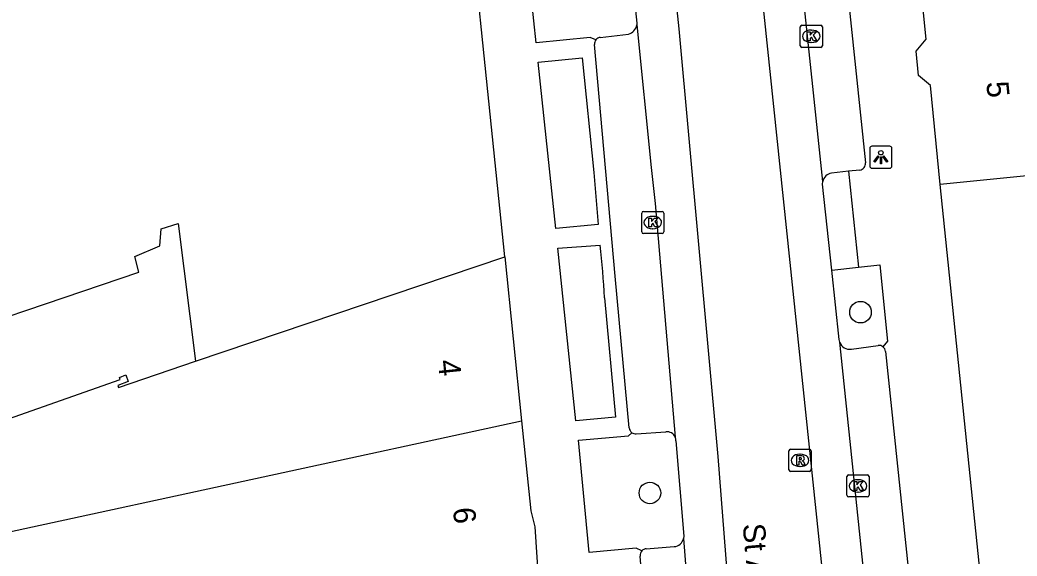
# Model space of a CAD drawing. Extents: x 159718 to 160783, y 383290 to 384030.
# Drawn here: x 160558.03 to 160603.13, y 383377.04 to 383401.3 of the extents above; entities that cross this region are included whole.
import ezdxf

# ---------------------------------------------------------------- set-up
doc = ezdxf.new("R2010")
doc.units = 0
for name, color, linetype in [('IMGEO_Boom', 7, 'Continuous'), ('IMGEO_Kolk', 7, 'Continuous'), ('IMGEO_Lichtpunt', 7, 'Continuous'), ('IMGEO_Openbare_ruimte_label', 7, 'Continuous'), ('IMGEO_Pand', 7, 'Continuous'), ('IMGEO_Pand_nummerreeks', 7, 'Continuous'), ('IMGEO_Parkeervlak_open', 7, 'Continuous'), ('IMGEO_Rijbaan_lokaal_gesloten', 7, 'Continuous'), ('IMGEO_Rioolput', 7, 'Continuous'), ('IMGEO_Voetpad_open', 7, 'Continuous')]:
    doc.layers.add(name, color=color, linetype=linetype)

msp = doc.modelspace()

# ---------------------------------------------------------------- linework, layer by layer
at = {"layer": 'IMGEO_Boom'}
for centre in [(160596.052, 383388.077), (160586.528, 383379.895)]:
    msp.add_circle(centre, 0.489, dxfattribs=at)
at = {"layer": 'IMGEO_Kolk'}
for p, q in [((160593.325, 383400.137), (160593.325, 383400.989)), ((160593.4, 383401.063), (160594.252, 383401.063)), ((160593.813, 383400.843), (160593.838, 383400.843)), ((160594.326, 383400.989), (160594.326, 383400.137)), ((160594.252, 383400.063), (160593.4, 383400.063)), ((160593.836, 383400.283), (160593.811, 383400.283)), ((160586.229, 383392.635), (160587.081, 383392.635)), ((160586.154, 383391.709), (160586.154, 383392.561)), ((160586.642, 383392.415), (160586.667, 383392.415)), ((160587.155, 383392.561), (160587.155, 383391.709)), ((160586.665, 383391.855), (160586.64, 383391.855)), ((160587.081, 383391.635), (160586.229, 383391.635)), ((160595.439, 383379.788), (160595.439, 383380.64)), ((160595.514, 383380.714), (160596.366, 383380.714)), ((160595.927, 383380.494), (160595.952, 383380.494)), ((160596.44, 383380.64), (160596.44, 383379.788)), ((160596.366, 383379.714), (160595.514, 383379.714)), ((160595.95, 383379.934), (160595.925, 383379.934))]:
    msp.add_line(p, q, dxfattribs=at)
for points in [[(160593.325, 383400.137), (160593.325, 383400.989)], [(160593.4, 383401.063), (160594.252, 383401.063)], [(160593.646, 383400.763), (160593.769, 383400.763), (160593.769, 383400.612), (160593.899, 383400.763), (160594.063, 383400.763), (160593.917, 383400.612), (160594.07, 383400.363), (160593.918, 383400.363), (160593.833, 383400.527), (160593.769, 383400.46), (160593.769, 383400.363), (160593.646, 383400.363), (160593.646, 383400.763)], [(160594.326, 383400.989), (160594.326, 383400.137)], [(160594.252, 383400.063), (160593.4, 383400.063)], [(160586.229, 383392.635), (160587.081, 383392.635)], [(160586.154, 383391.709), (160586.154, 383392.561)], [(160586.475, 383392.335), (160586.598, 383392.335), (160586.598, 383392.184), (160586.728, 383392.335), (160586.892, 383392.335), (160586.746, 383392.184), (160586.899, 383391.935), (160586.747, 383391.935), (160586.662, 383392.099), (160586.598, 383392.032), (160586.598, 383391.935), (160586.475, 383391.935), (160586.475, 383392.335)], [(160587.155, 383392.561), (160587.155, 383391.709)], [(160587.081, 383391.635), (160586.229, 383391.635)], [(160595.439, 383379.788), (160595.439, 383380.64)], [(160595.514, 383380.714), (160596.366, 383380.714)], [(160596.44, 383380.64), (160596.44, 383379.788)], [(160595.76, 383380.414), (160595.883, 383380.414), (160595.883, 383380.263), (160596.013, 383380.414), (160596.177, 383380.414), (160596.031, 383380.263), (160596.184, 383380.014), (160596.032, 383380.014), (160595.947, 383380.178), (160595.883, 383380.111), (160595.883, 383380.014), (160595.76, 383380.014), (160595.76, 383380.414)], [(160596.366, 383379.714), (160595.514, 383379.714)]]:
    msp.add_lwpolyline(points, dxfattribs=at)
for centre, start, end in [((160593.402, 383400.987), 91.552, 178.448), ((160593.402, 383400.987), 91.552, 178.448), ((160594.25, 383400.987), 1.552, 88.448), ((160594.25, 383400.987), 1.552, 88.448), ((160593.402, 383400.139), 181.552, 268.448), ((160593.402, 383400.139), 181.552, 268.448), ((160594.25, 383400.139), 271.552, 358.448), ((160594.25, 383400.139), 271.552, 358.448), ((160586.231, 383392.559), 91.552, 178.448), ((160586.231, 383392.559), 91.552, 178.448), ((160587.079, 383392.559), 1.552, 88.448), ((160587.079, 383392.559), 1.552, 88.448), ((160586.231, 383391.711), 181.552, 268.448), ((160586.231, 383391.711), 181.552, 268.448), ((160587.079, 383391.711), 271.552, 358.448), ((160587.079, 383391.711), 271.552, 358.448), ((160595.516, 383380.638), 91.552, 178.448), ((160595.516, 383380.638), 91.552, 178.448), ((160596.364, 383380.638), 1.552, 88.448), ((160596.364, 383380.638), 1.552, 88.448), ((160595.516, 383379.79), 181.552, 268.448), ((160595.516, 383379.79), 181.552, 268.448), ((160596.364, 383379.79), 271.552, 358.448), ((160596.364, 383379.79), 271.552, 358.448)]:
    msp.add_arc(centre, 0.0765, start, end, dxfattribs=at)
for centre, major_axis, ratio, start_param, end_param in [((160593.812, 383400.563), (-0.387, 0.002), 0.722429, 4.712389, 7.853982), ((160593.837, 383400.563), (-0.39, 0.002), 0.717154, 1.570796, 4.712389), ((160586.641, 383392.135), (-0.387, 0.002), 0.722429, 4.712389, 7.853982), ((160586.666, 383392.135), (-0.39, 0.002), 0.717154, 1.570796, 4.712389), ((160595.926, 383380.214), (-0.387, 0.002), 0.722429, 4.712389, 7.853982), ((160595.951, 383380.214), (-0.39, 0.002), 0.717154, 1.570796, 4.712389)]:
    msp.add_ellipse(centre, major_axis=major_axis, ratio=ratio, start_param=start_param, end_param=end_param, dxfattribs=at)
at = {"layer": 'IMGEO_Lichtpunt'}
for p, q in [((160596.473, 383395.493), (160596.473, 383394.686)), ((160596.473, 383395.493), (160596.473, 383394.686)), ((160597.375, 383395.588), (160596.567, 383395.588)), ((160597.375, 383395.588), (160596.567, 383395.588)), ((160597.469, 383394.686), (160597.469, 383395.493)), ((160597.469, 383394.686), (160597.469, 383395.493)), ((160596.567, 383394.592), (160597.375, 383394.592)), ((160596.567, 383394.592), (160597.375, 383394.592))]:
    msp.add_line(p, q, dxfattribs=at)
for points in [[(160596.847, 383395.157), (160596.886, 383395.129), (160596.698, 383394.867), (160596.66, 383394.894), (160596.847, 383395.157)], [(160596.949, 383395.109), (160596.996, 383395.109), (160596.996, 383394.787), (160596.949, 383394.787), (160596.949, 383395.109)], [(160597.059, 383395.129), (160597.097, 383395.156), (160597.284, 383394.894), (160597.245, 383394.866), (160597.059, 383395.129)]]:
    msp.add_lwpolyline(points, dxfattribs=at)
msp.add_circle((160596.972, 383395.291), 0.0994, dxfattribs=at)
for centre, start, end in [((160596.567, 383395.493), 90, 180), ((160596.567, 383395.493), 90, 180), ((160597.375, 383395.493), 0, 90), ((160597.375, 383395.493), 0, 90), ((160596.567, 383394.686), 180, 270), ((160596.567, 383394.686), 180, 270), ((160597.375, 383394.686), 270, 0), ((160597.375, 383394.686), 270, 360)]:
    msp.add_arc(centre, 0.0946, start, end, dxfattribs=at)
at = {"layer": 'IMGEO_Pand'}
for points in [[(160579.957, 383390.583), (160577.746, 383412.172)], [(160598.855, 383402.07), (160603.832, 383402.557), (160608.051, 383402.97), (160608.854, 383394.759), (160604.635, 383394.346), (160599.658, 383393.859)], [(160599.658, 383393.859), (160599.22, 383398.338), (160598.675, 383398.788), (160598.568, 383399.883), (160599.016, 383400.428), (160598.855, 383402.07)], [(160549.349, 383392.067), (160551.487, 383387.889), (160552.375, 383386.153), (160563.405, 383389.892), (160563.227, 383390.604), (160564.354, 383391.079), (160564.414, 383391.85), (160565.184, 383392.087), (160565.969, 383385.858)], [(160565.969, 383385.858), (160579.957, 383390.583)], [(160579.957, 383390.583), (160580.717, 383383.161)], [(160556.424, 383382.88), (160562.566, 383385.031), (160562.53, 383385.125), (160562.818, 383385.235), (160562.932, 383384.936), (160562.466, 383384.757), (160562.498, 383384.673), (160565.969, 383385.858)], [(160557.355, 383378.088), (160580.717, 383383.161)], [(160580.717, 383383.161), (160581.134, 383379.085), (160581.318, 383378.369), (160581.518, 383375.387)]]:
    msp.add_lwpolyline(points, dxfattribs=at)
at = {"layer": 'IMGEO_Parkeervlak_open'}
for points in [[(160584.282, 383400.513), (160585.56, 383400.664)], [(160595.638, 383386.406), (160596.852, 383386.57)], [(160585.902, 383382.567), (160587.252, 383382.661)], [(160586.364, 383377.369), (160587.627, 383377.465)]]:
    msp.add_lwpolyline(points, dxfattribs=at)
for centre, radius, start, end in [((160585.425, 383401.161), 0.514, 285.1689, 350.6577), ((160584.313, 383400.225), 0.29, 96.0994, 142.8335), ((160595.558, 383386.872), 0.473, 198.121, 279.697), ((160596.888, 383386.274), 0.298, 53.2546, 96.9159), ((160585.888, 383382.862), 0.295, 234.0169, 272.8084), ((160587.304, 383382.264), 0.4, 22.6188, 97.3944), ((160587.573, 383377.952), 0.49, 276.3048, 346.5067), ((160586.378, 383377.069), 0.3, 92.604, 134.8368)]:
    msp.add_arc(centre, radius, start, end, dxfattribs=at)
at = {"layer": 'IMGEO_Rijbaan_lokaal_gesloten'}
for points in [[(160595.764, 383362.66), (160589.375, 383423.771), (160591.203, 383423.954)], [(160583.596, 383423.202), (160585.479, 383423.384), (160587.833, 383400.9), (160589.592, 383381.539), (160591.203, 383361.107), (160591.724, 383354.429), (160592.324, 383346.798), (160592.528, 383341.495), (160592.558, 383339.696), (160592.568, 383337.896)], [(160594.344, 383393.985), (160592.388, 383412.622)], [(160585.59, 383404.462), (160585.608, 383404.352), (160585.94, 383401.161), (160585.933, 383401.077)], [(160585.933, 383401.077), (160586.585, 383394.618), (160586.757, 383392.992), (160587.673, 383382.418)], [(160594.753, 383389.974), (160594.337, 383393.864), (160594.344, 383393.985)], [(160595.109, 383386.725), (160595.087, 383386.843), (160594.753, 383389.974)], [(160597.045, 383368.17), (160595.109, 383386.725)], [(160587.703, 383382.261), (160588.063, 383377.941), (160588.05, 383377.838)], [(160588.05, 383377.838), (160589.191, 383363.167)]]:
    msp.add_lwpolyline(points, dxfattribs=at)
msp.add_arc((160587.307, 383382.267), 0.396, 359.1875, 22.4481, dxfattribs=at)
at = {"layer": 'IMGEO_Rioolput'}
for p, q in [((160592.891, 383381.872), (160593.743, 383381.872)), ((160592.816, 383380.946), (160592.816, 383381.798)), ((160593.304, 383381.652), (160593.329, 383381.652)), ((160593.817, 383381.798), (160593.817, 383380.946)), ((160593.327, 383381.092), (160593.302, 383381.092)), ((160593.743, 383380.872), (160592.891, 383380.872))]:
    msp.add_line(p, q, dxfattribs=at)
for points in [[(160592.891, 383381.872), (160593.743, 383381.872)], [(160592.816, 383380.946), (160592.816, 383381.798)], [(160593.405, 383381.57), (160593.153, 383381.572), (160593.153, 383381.172)], [(160593.331, 383381.491), (160593.277, 383381.491), (160593.277, 383381.41)], [(160593.277, 383381.41), (160593.329, 383381.41)], [(160593.817, 383381.798), (160593.817, 383380.946)], [(160593.153, 383381.172), (160593.277, 383381.172), (160593.277, 383381.334), (160593.288, 383381.334)], [(160593.335, 383381.305), (160593.406, 383381.172), (160593.546, 383381.172), (160593.481, 383381.298)], [(160593.743, 383380.872), (160592.891, 383380.872)]]:
    msp.add_lwpolyline(points, dxfattribs=at)
for centre, radius, start, end in [((160592.893, 383381.796), 0.0765, 91.552, 178.448), ((160592.893, 383381.796), 0.0765, 91.552, 178.448), ((160593.741, 383381.796), 0.0765, 1.552, 88.448), ((160593.741, 383381.796), 0.0765, 1.552, 88.448), ((160593.313, 383381.599), 0.19, 274.7715, 282.9687), ((160593.337, 383381.395), 0.0964, 77.0061, 93.1865), ((160593.351, 383381.452), 0.0378, 276.6634, 79.6772), ((160593.404, 383381.46), 0.109, 350.3612, 89.416), ((160593.402, 383381.46), 0.112, 277.5842, 350.9817), ((160592.893, 383380.948), 0.0765, 181.552, 268.448), ((160592.893, 383380.948), 0.0765, 181.552, 268.448), ((160593.287, 383381.281), 0.0533, 26.0293, 88.6989), ((160593.386, 383381.245), 0.108, 29.5134, 73.7905), ((160593.741, 383380.948), 0.0765, 271.552, 358.448), ((160593.741, 383380.948), 0.0765, 271.552, 358.448)]:
    msp.add_arc(centre, radius, start, end, dxfattribs=at)
for centre, major_axis, ratio, start_param, end_param in [((160593.303, 383381.372), (-0.387, 0.002), 0.722429, 4.712389, 7.853982), ((160593.328, 383381.372), (-0.39, 0.002), 0.717154, 1.570796, 4.712389)]:
    msp.add_ellipse(centre, major_axis=major_axis, ratio=ratio, start_param=start_param, end_param=end_param, dxfattribs=at)
at = {"layer": 'IMGEO_Voetpad_open'}
for points in [[(160594.469, 383412.117), (160596.274, 383394.841)], [(160584.082, 383400.4), (160583.83, 383400.504), (160581.386, 383400.271), (160580.967, 383404.269), (160583.39, 383404.513), (160583.637, 383404.679)], [(160585.593, 383382.837), (160584.957, 383389.713), (160584.026, 383400.192)], [(160582.272, 383391.857), (160581.479, 383399.386), (160583.462, 383399.585), (160583.997, 383394.402), (160584.184, 383392.038), (160582.272, 383391.857)], [(160595.506, 383394.453), (160594.742, 383394.375)], [(160596.018, 383394.505), (160595.506, 383394.453)], [(160595.506, 383394.453), (160595.966, 383390.116)], [(160603.47, 383356.793), (160599.658, 383393.859)], [(160583.171, 383383.159), (160582.366, 383390.977), (160584.277, 383391.114)], [(160594.753, 383389.974), (160595.966, 383390.116)], [(160595.966, 383390.116), (160596.92, 383390.227), (160597.279, 383386.771), (160597.066, 383386.513)], [(160584.479, 383388.723), (160584.963, 383383.32), (160583.171, 383383.159)], [(160597.183, 383386.298), (160598.992, 383369.001)], [(160586.166, 383377.282), (160585.902, 383377.397), (160583.779, 383377.2), (160583.294, 383382.286), (160585.551, 383382.48), (160585.714, 383382.623)], [(160587.115, 383363.67), (160586.723, 383369.18), (160586.079, 383377.039)]]:
    msp.add_lwpolyline(points, dxfattribs=at)
for centre, radius, start, end in [((160584.316, 383400.226), 0.292, 143.2628, 186.6002), ((160595.979, 383394.8), 0.298, 277.5059, 7.8862), ((160594.819, 383393.898), 0.483, 99.188, 169.6487), ((160530.677, 383385.382), 53.905, 3.5538, 6.1044), ((160596.889, 383386.277), 0.295, 4.0152, 53.0936), ((160585.887, 383382.862), 0.295, 184.8365, 234.133), ((160586.378, 383377.069), 0.301, 134.8931, 185.7097)]:
    msp.add_arc(centre, radius, start, end, dxfattribs=at)

# ---------------------------------------------------------------- texts
at = {"layer": 'IMGEO_Openbare_ruimte_label'}
msp.add_text('St Antoniusstraat', height=1, rotation=274.9921, dxfattribs=at).set_placement((160590.723, 383378.479))
at = {"layer": 'IMGEO_Pand_nummerreeks'}
for s, rotation, p in [('5', 275.5855, (160601.738, 383398.484)), ('4', 275.7133, (160576.937, 383385.885)), ('6', 275.8443, (160577.614, 383379.197))]:
    msp.add_text(s, height=1, rotation=rotation, dxfattribs=at).set_placement(p)

doc.saveas('drawing.dxf')
